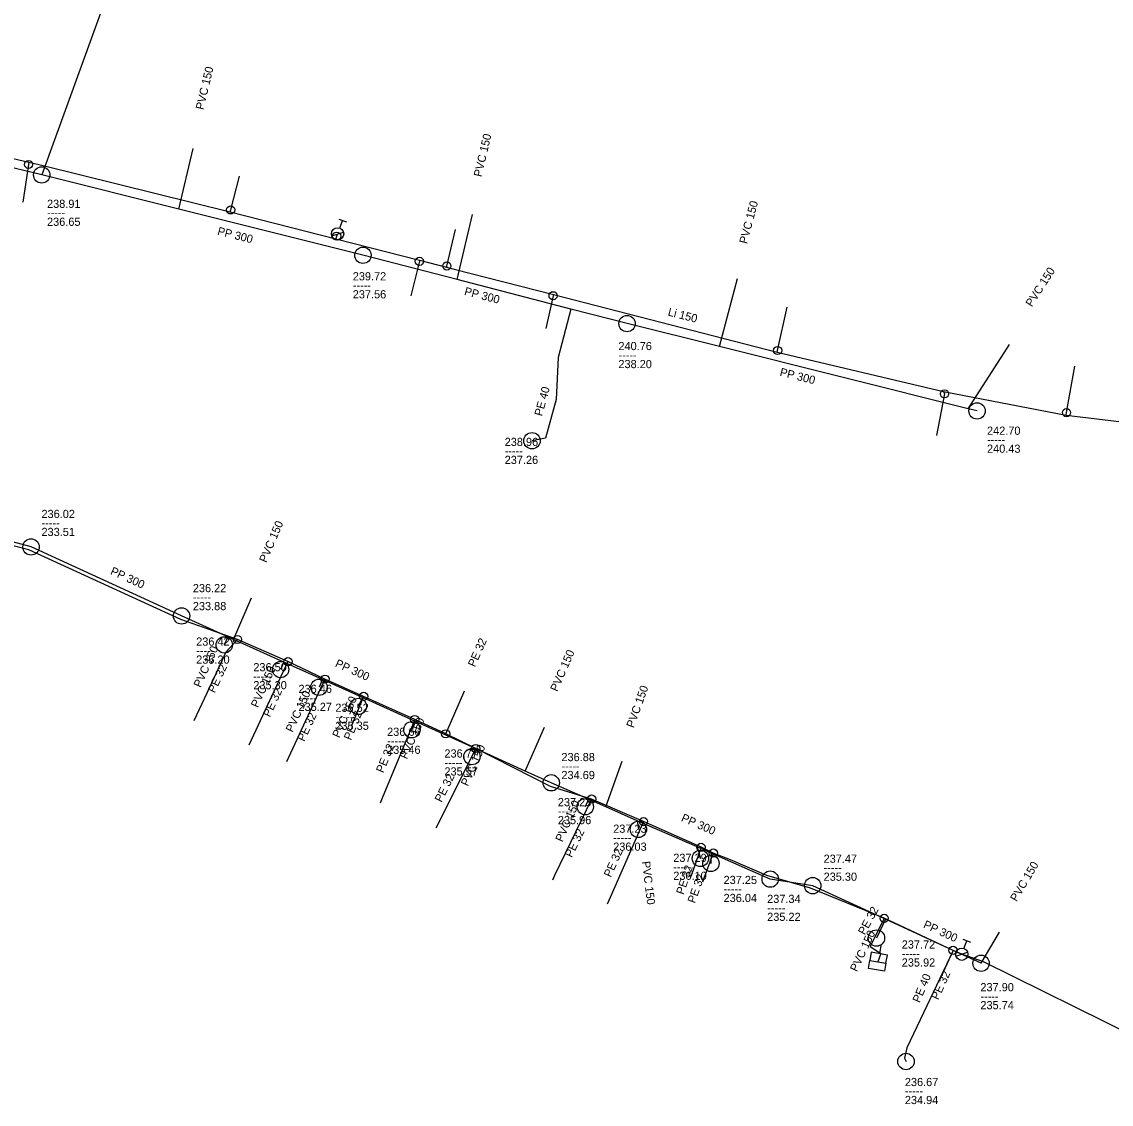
# Model space of a CAD drawing. Extents: x -771681 to -770485, y -1050143 to -1049574.
# Drawn here: x -771433.4 to -771300.2, y -1049953.5 to -1049821.1 of the extents above; entities that cross this region are included whole.
import ezdxf

# ---------------------------------------------------------------- set-up
doc = ezdxf.new("R2010")
doc.units = 0
doc.layers.add('Level 0', color=7, linetype='Continuous')

msp = doc.modelspace()

# ---------------------------------------------------------------- linework, layer by layer
at = {"layer": 'Level 0'}
for p, q in [((-771415.79, -1049797.97), (-771430.98, -1049839.82)), ((-771440.27, -1049836.44), (-771432.55, -1049838.26)), ((-771430.98, -1049839.82), (-771442.79, -1049836.98)), ((-771414.22, -1049844.01), (-771412.47, -1049836.6)), ((-771432.59, -1049838.54), (-771433.31, -1049843.16)), ((-771432.55, -1049838.26), (-771432.59, -1049838.54)), ((-771432.55, -1049838.26), (-771430.82, -1049838.67)), ((-771430.82, -1049838.67), (-771407.93, -1049844.33)), ((-771414.22, -1049844.01), (-771430.98, -1049839.82)), ((-771407.87, -1049844.1), (-771406.81, -1049839.97)), ((-771391.7, -1049849.65), (-771414.22, -1049844.01)), ((-771407.93, -1049844.33), (-771407.87, -1049844.1)), ((-771407.93, -1049844.33), (-771395.03, -1049847.63)), ((-771394.66, -1049845.22), (-771393.72, -1049845.57)), ((-771394.53, -1049846.34), (-771394.19, -1049845.4)), ((-771380.17, -1049852.61), (-771378.29, -1049844.67)), ((-771395.5, -1049847.27), (-771394.08, -1049846.81)), ((-771394.9, -1049847.31), (-771394.79, -1049847.04)), ((-771381.43, -1049850.96), (-771380.38, -1049846.51)), ((-771395.03, -1049847.63), (-771394.9, -1049847.31)), ((-771395.03, -1049847.63), (-771384.76, -1049850.25)), ((-771380.17, -1049852.61), (-771391.7, -1049849.65)), ((-771384.79, -1049850.38), (-771385.84, -1049854.62)), ((-771384.76, -1049850.25), (-771384.79, -1049850.38)), ((-771384.76, -1049850.25), (-771381.46, -1049851.09)), ((-771381.46, -1049851.09), (-771381.43, -1049850.96)), ((-771381.46, -1049851.09), (-771380.52, -1049851.33)), ((-771380.52, -1049851.33), (-771368.41, -1049854.44)), ((-771348.09, -1049860.82), (-771345.88, -1049852.5)), ((-771366.29, -1049856.22), (-771380.17, -1049852.61)), ((-771368.44, -1049854.6), (-771369.32, -1049858.61)), ((-771368.41, -1049854.44), (-771368.44, -1049854.6)), ((-771368.41, -1049854.44), (-771341.02, -1049861.49)), ((-771366.29, -1049856.22), (-771367.83, -1049862.14)), ((-771359.4, -1049858), (-771366.29, -1049856.22)), ((-771340.98, -1049861.3), (-771339.82, -1049856)), ((-771348.09, -1049860.82), (-771359.4, -1049858)), ((-771317.67, -1049868.41), (-771348.09, -1049860.82)), ((-771341.02, -1049861.49), (-771340.98, -1049861.3)), ((-771341.02, -1049861.49), (-771320.68, -1049866.32)), ((-771317.67, -1049868.41), (-771312.63, -1049860.54)), ((-771367.83, -1049862.14), (-771368.05, -1049867.27)), ((-771305.65, -1049868.89), (-771304.65, -1049863.22)), ((-771320.57, -1049866.59), (-771321.55, -1049871.67)), ((-771320.68, -1049866.32), (-771320.57, -1049866.59)), ((-771320.68, -1049866.32), (-771305.7, -1049869.19)), ((-771368.05, -1049867.27), (-771369.35, -1049872.02)), ((-771316.59, -1049868.68), (-771317.67, -1049868.41)), ((-771305.7, -1049869.19), (-771305.65, -1049868.89)), ((-771305.7, -1049869.19), (-771292.13, -1049870.85)), ((-771369.35, -1049872.02), (-771371.02, -1049872.33)), ((-771432.55, -1049885.68), (-771452.13, -1049880.59)), ((-771432.29, -1049885.31), (-771441.39, -1049882.88)), ((-771413.97, -1049894.18), (-771432.55, -1049885.68)), ((-771413.88, -1049893.75), (-771432.29, -1049885.31)), ((-771407.52, -1049896.62), (-771405.32, -1049891.52)), ((-771408.21, -1049896.31), (-771413.88, -1049893.75)), ((-771407.03, -1049896.64), (-771413.97, -1049894.18)), ((-771408.21, -1049896.31), (-771408.65, -1049897.29)), ((-771407.52, -1049896.62), (-771408.21, -1049896.31)), ((-771407.03, -1049896.64), (-771408.46, -1049898.18)), ((-771401.36, -1049899.4), (-771407.52, -1049896.62)), ((-771400.87, -1049899.34), (-771407.03, -1049896.64)), ((-771408.46, -1049898.18), (-771410.19, -1049901.89)), ((-771400.87, -1049899.34), (-771405.65, -1049909.56)), ((-771401.36, -1049899.4), (-771401.77, -1049900.31)), ((-771396.64, -1049901.53), (-771401.36, -1049899.4)), ((-771396.34, -1049901.49), (-771400.87, -1049899.34)), ((-771396.34, -1049901.49), (-771400.82, -1049911.07)), ((-771396.64, -1049901.53), (-771397.07, -1049902.48)), ((-771391.77, -1049903.73), (-771396.64, -1049901.53)), ((-771391.61, -1049903.59), (-771396.34, -1049901.49)), ((-771410.19, -1049901.89), (-771412.38, -1049906.58)), ((-771381.57, -1049908.17), (-771379.36, -1049903.1)), ((-771379.36, -1049903.1), (-771379.28, -1049902.92)), ((-771391.61, -1049903.59), (-771393.14, -1049907.29)), ((-771391.77, -1049903.73), (-771392.26, -1049904.82)), ((-771385.26, -1049906.67), (-771391.77, -1049903.73)), ((-771385.37, -1049906.42), (-771391.61, -1049903.59)), ((-771385.37, -1049906.42), (-771389.35, -1049916.05)), ((-771385.26, -1049906.67), (-771385.71, -1049907.67)), ((-771381.57, -1049908.17), (-771385.37, -1049906.42)), ((-771377.93, -1049909.98), (-771385.26, -1049906.67)), ((-771377.9, -1049909.97), (-771381.57, -1049908.17)), ((-771371.84, -1049912.73), (-771369.51, -1049907.37)), ((-771400.82, -1049911.07), (-771401.06, -1049911.59)), ((-771377.9, -1049909.97), (-771382.79, -1049919.72)), ((-771377.93, -1049909.98), (-771378.36, -1049910.95)), ((-771371.84, -1049912.73), (-771377.93, -1049909.98)), ((-771368.75, -1049914.61), (-771377.9, -1049909.97)), ((-771362, -1049917.09), (-771360, -1049911.53)), ((-771368.67, -1049914.16), (-771371.84, -1049912.73)), ((-771363.73, -1049916.15), (-771368.75, -1049914.61)), ((-771364.1, -1049916.17), (-771368.67, -1049914.16)), ((-771389.35, -1049916.05), (-771389.6, -1049916.65)), ((-771363.73, -1049916.15), (-771368.26, -1049925.5)), ((-771364.1, -1049916.17), (-771364.5, -1049917.08)), ((-771362, -1049917.09), (-771364.1, -1049916.17)), ((-771357.39, -1049918.91), (-771363.73, -1049916.15)), ((-771358.14, -1049918.79), (-771362, -1049917.09)), ((-771357.39, -1049918.91), (-771361.64, -1049928.57)), ((-771350.82, -1049922.01), (-771358.14, -1049918.79)), ((-771358.14, -1049918.79), (-771358.01, -1049919.85)), ((-771350.35, -1049922.04), (-771357.39, -1049918.91)), ((-771350.35, -1049922.04), (-771351.53, -1049925.42)), ((-771349.09, -1049922.77), (-771350.82, -1049922.01)), ((-771350.82, -1049922.01), (-771350.43, -1049923.4)), ((-771348.85, -1049922.75), (-771350.35, -1049922.04)), ((-771348.85, -1049922.75), (-771350.09, -1049926.07)), ((-771349.09, -1049922.77), (-771349.14, -1049924.02)), ((-771341.89, -1049925.94), (-771349.09, -1049922.77)), ((-771346.76, -1049923.59), (-771348.85, -1049922.75)), ((-771342.32, -1049925.5), (-771346.76, -1049923.59)), ((-771368.26, -1049925.5), (-771368.53, -1049926.06)), ((-771351.53, -1049925.42), (-771351.62, -1049925.69)), ((-771336.95, -1049927.06), (-771342.32, -1049925.5)), ((-771350.09, -1049926.07), (-771350.18, -1049926.32)), ((-771336.69, -1049926.74), (-771341.89, -1049925.94)), ((-771327.95, -1049930.73), (-771336.95, -1049927.06)), ((-771327.8, -1049930.84), (-771336.69, -1049926.74)), ((-771361.64, -1049928.57), (-771361.83, -1049928.99)), ((-771327.95, -1049930.73), (-771329.65, -1049934.19)), ((-771327.8, -1049930.84), (-771328.89, -1049933.15)), ((-771319.53, -1049934.65), (-771327.95, -1049930.73)), ((-771319.53, -1049934.65), (-771327.8, -1049930.84)), ((-771316.1, -1049936.23), (-771313.84, -1049932.43)), ((-771318.33, -1049933.3), (-771317.39, -1049933.65)), ((-771318.2, -1049934.42), (-771317.86, -1049933.48)), ((-771329.65, -1049934.19), (-771328.34, -1049935.02)), ((-771328.34, -1049935.02), (-771328.71, -1049936.04)), ((-771328.36, -1049934.07), (-771328.54, -1049935.06)), ((-771319.53, -1049934.65), (-771325.18, -1049946.58)), ((-771319.53, -1049934.65), (-771321.3, -1049938.55)), ((-771318.46, -1049935.12), (-771319.53, -1049934.65)), ((-771316.1, -1049936.23), (-771319.53, -1049934.65)), ((-771319.17, -1049935.35), (-771317.75, -1049934.89)), ((-771315.8, -1049936.07), (-771318.46, -1049935.12)), ((-771296.77, -1049945.49), (-771315.8, -1049936.07)), ((-771325.18, -1049946.58), (-771325.48, -1049947.83)), ((-771325.48, -1049947.83), (-771325.28, -1049948.24))]:
    msp.add_line(p, q, dxfattribs=at)
msp.add_lwpolyline([(-771327.55, -1049935.23), (-771329.52, -1049934.88), (-771329.69, -1049935.87), (-771327.73, -1049936.21)], close=True, dxfattribs=at)
msp.add_lwpolyline([(-771327.73, -1049936.21), (-771327.9, -1049937.2), (-771329.87, -1049936.85), (-771329.69, -1049935.87)], dxfattribs=at)
for centre, radius in [((-771432.59, -1049838.54), 0.5), ((-771430.98, -1049839.82), 1), ((-771407.87, -1049844.1), 0.5), ((-771394.79, -1049847.04), 0.75), ((-771394.9, -1049847.31), 0.5), ((-771391.7, -1049849.65), 1), ((-771384.79, -1049850.38), 0.5), ((-771381.43, -1049850.96), 0.5), ((-771368.44, -1049854.6), 0.5), ((-771359.4, -1049858), 1), ((-771340.98, -1049861.3), 0.5), ((-771320.57, -1049866.59), 0.5), ((-771316.59, -1049868.68), 1), ((-771305.65, -1049868.89), 0.5), ((-771371.02, -1049872.33), 1), ((-771432.29, -1049885.31), 1), ((-771413.88, -1049893.75), 1), ((-771408.65, -1049897.29), 1), ((-771407.03, -1049896.64), 0.5), ((-771400.87, -1049899.34), 0.5), ((-771401.77, -1049900.31), 1), ((-771397.07, -1049902.48), 1), ((-771396.34, -1049901.49), 0.5), ((-771391.61, -1049903.59), 0.5), ((-771392.26, -1049904.82), 1), ((-771385.71, -1049907.67), 1), ((-771385.37, -1049906.42), 0.5), ((-771381.57, -1049908.17), 0.5), ((-771377.9, -1049909.97), 0.5), ((-771378.36, -1049910.95), 1), ((-771368.67, -1049914.16), 1), ((-771364.5, -1049917.08), 1), ((-771363.73, -1049916.15), 0.5), ((-771358.01, -1049919.85), 1), ((-771357.39, -1049918.91), 0.5), ((-771350.35, -1049922.04), 0.5), ((-771350.43, -1049923.4), 1), ((-771349.14, -1049924.02), 1), ((-771348.85, -1049922.75), 0.5), ((-771341.89, -1049925.94), 1), ((-771336.69, -1049926.74), 1), ((-771327.95, -1049930.73), 0.5), ((-771328.89, -1049933.15), 1), ((-771319.53, -1049934.65), 0.5), ((-771318.46, -1049935.12), 0.75), ((-771316.1, -1049936.23), 1), ((-771325.28, -1049948.24), 1)]:
    msp.add_circle(centre, radius, dxfattribs=at)

# ---------------------------------------------------------------- texts
for s, rotation, p in [('PVC 150', 76.712, (-771411.2, -1049831.92)), ('PVC 150', 76.679, (-771377.2, -1049840.13)), ('PVC 150', 75.124, (-771344.73, -1049848.32)), ('PP 300', 345.94, (-771409.56, -1049847.13)), ('PVC 150', 57.364, (-771309.89, -1049856.04)), ('PP 300', 345.421, (-771379.37, -1049854.48)), ('Li 150', 345.566, (-771354.47, -1049857)), ('PP 300', 345.99, (-771340.78, -1049864.37)), ('PE 40', 74.694, (-771369.79, -1049869.39)), ('PVC 150', 66.666, (-771403.52, -1049887.31)), ('PP 300', 335.371, (-771422.67, -1049888.62)), ('PE 32', 66.038, (-771378, -1049900.08)), ('PVC 150', 65.821, (-771411.55, -1049902.59)), ('PP 300', 335.689, (-771395.18, -1049899.91)), ('PVC 150', 66.505, (-771367.92, -1049903.08)), ('PE 32', 65, (-771409.82, -1049903.25)), ('PVC 150', 65.746, (-771404.54, -1049905.05)), ('PE 32', 64.934, (-771403.08, -1049906.2)), ('PVC 150', 65.647, (-771400.29, -1049908.06)), ('PVC 150', 70.216, (-771358.58, -1049907.52)), ('PVC 150', 65.794, (-771394.59, -1049908.74)), ('PE 32', 65.225, (-771398.86, -1049909.19)), ('PE 32', 67.534, (-771393.16, -1049909.03)), ('PVC 150', 65.772, (-771386.33, -1049911.34)), ('PE 32', 67.38, (-771389.22, -1049913.02)), ('PVC 150', 66.092, (-771378.86, -1049914.65)), ('PE 32', 63.364, (-771382.09, -1049916.62)), ('PVC 150', 66.272, (-771367.3, -1049921.47)), ('PP 300', 336.256, (-771352.86, -1049918.8)), ('PE 32', 64.259, (-771366.15, -1049923.38)), ('PE 32', 65.659, (-771361.38, -1049925.79)), ('PVC 150', 276.992, (-771357.58, -1049923.8)), ('PE 32', 71.565, (-771352.48, -1049927.9)), ('PVC 150', 59.258, (-771311.75, -1049928.77)), ('PE 32', 70.201, (-771351.1, -1049928.96)), ('PE 32', 61.476, (-771330.33, -1049932.84)), ('PP 300', 335.264, (-771323.25, -1049931.84)), ('PVC 150', 64.739, (-771331.28, -1049937.34)), ('PE 40', 67.162, (-771323.61, -1049941.13)), ('PE 32', 65.589, (-771321.33, -1049940.78))]:
    msp.add_text(s, height=1, rotation=rotation, dxfattribs=at).set_placement(p)
for s, p in [('238.91', (-771430.33, -1049843.85)), ('-----', (-771430.33, -1049844.95)), ('236.65', (-771430.33, -1049846.05)), ('239.72', (-771392.94, -1049852.72)), ('-----', (-771392.94, -1049853.82)), ('237.56', (-771392.94, -1049854.92)), ('240.76', (-771360.45, -1049861.25)), ('-----', (-771360.45, -1049862.35)), ('238.20', (-771360.45, -1049863.45)), ('242.70', (-771315.37, -1049871.6)), ('238.96', (-771374.36, -1049872.97)), ('-----', (-771315.37, -1049872.7)), ('-----', (-771374.36, -1049874.07)), ('240.43', (-771315.37, -1049873.8)), ('237.26', (-771374.36, -1049875.17)), ('236.02', (-771431.01, -1049881.78)), ('-----', (-771431.01, -1049882.88)), ('233.51', (-771431.01, -1049883.98)), ('236.22', (-771412.5, -1049890.85)), ('-----', (-771412.5, -1049891.95)), ('233.88', (-771412.5, -1049893.05)), ('236.42', (-771412.09, -1049897.39)), ('-----', (-771412.09, -1049898.49)), ('235.20', (-771412.09, -1049899.59)), ('236.50', (-771405.1, -1049900.52)), ('-----', (-771405.1, -1049901.62)), ('235.30', (-771405.1, -1049902.72)), ('236.46', (-771399.58, -1049903.17)), ('-----', (-771399.58, -1049904.27)), ('235.27', (-771399.58, -1049905.37)), ('236.52', (-771395.07, -1049905.48)), ('-----', (-771395.07, -1049906.58)), ('235.35', (-771395.07, -1049907.68)), ('236.66', (-771388.74, -1049908.42)), ('-----', (-771388.74, -1049909.52)), ('235.46', (-771388.74, -1049910.62)), ('236.77', (-771381.73, -1049911.07)), ('236.88', (-771367.42, -1049911.51)), ('-----', (-771381.73, -1049912.17)), ('235.57', (-771381.73, -1049913.27)), ('-----', (-771367.42, -1049912.61)), ('234.69', (-771367.42, -1049913.71)), ('237.23', (-771367.86, -1049917.02)), ('-----', (-771367.86, -1049918.12)), ('235.96', (-771367.86, -1049919.22)), ('237.23', (-771361.09, -1049920.27)), ('-----', (-771361.09, -1049921.37)), ('236.03', (-771361.09, -1049922.47)), ('237.29', (-771353.74, -1049923.83)), ('237.47', (-771335.36, -1049923.94)), ('-----', (-771353.74, -1049924.93)), ('236.10', (-771353.74, -1049926.03)), ('237.25', (-771347.59, -1049926.54)), ('-----', (-771335.36, -1049925.04)), ('235.30', (-771335.36, -1049926.14)), ('-----', (-771347.59, -1049927.64)), ('236.04', (-771347.59, -1049928.74)), ('237.34', (-771342.26, -1049928.85)), ('-----', (-771342.26, -1049929.95)), ('235.22', (-771342.26, -1049931.05)), ('237.72', (-771325.8, -1049934.43)), ('-----', (-771325.8, -1049935.53)), ('235.92', (-771325.8, -1049936.63)), ('237.90', (-771316.18, -1049939.65)), ('-----', (-771316.18, -1049940.75)), ('235.74', (-771316.18, -1049941.85)), ('236.67', (-771325.42, -1049951.25)), ('-----', (-771325.42, -1049952.35)), ('234.94', (-771325.42, -1049953.45))]:
    msp.add_text(s, height=1, dxfattribs=at).set_placement(p)

doc.saveas('drawing.dxf')
